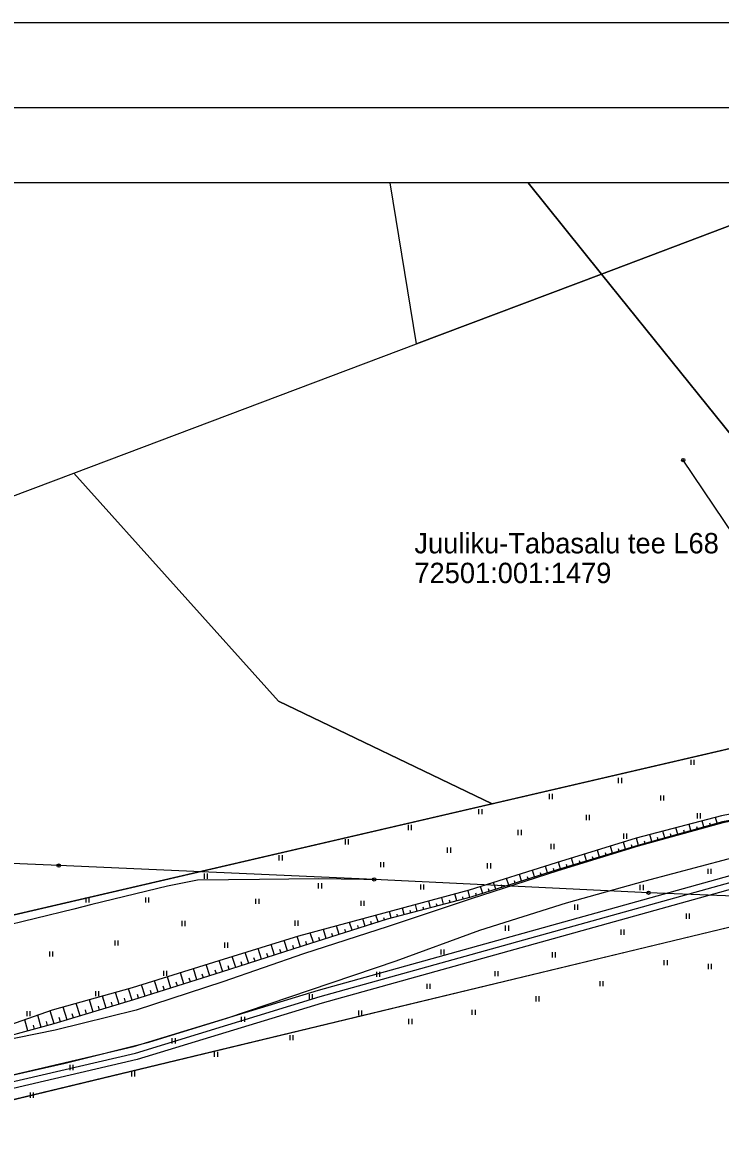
# Model space of a CAD drawing. Extents: x 532656 to 533339, y 6581345 to 6581629.
# Drawn here: x 533136.1 to 533238.9, y 6581463.1 to 6581629 of the extents above; entities that cross this region are included whole.
import ezdxf

# ---------------------------------------------------------------- set-up
doc = ezdxf.new("R2010")
doc.units = 0
for name, color, linetype in [('HALJASTUS', 7, 'Continuous'), ('KASUTUSALA', 7, 'Continuous'), ('KPOHULIIN', 7, 'Continuous'), ('MPKAABEL', 7, 'Continuous'), ('MPOHULIIN', 7, 'Continuous'), ('PIIR', 7, 'Continuous'), ('POST', 7, 'Continuous'), ('PR_SIDE', 7, 'Continuous'), ('RELJEEF', 7, 'Continuous'), ('TEE', 7, 'Continuous'), ('VORMISTUS', 7, 'Continuous')]:
    doc.layers.add(name, color=color, linetype=linetype)

msp = doc.modelspace()

# ---------------------------------------------------------------- linework, layer by layer
at = {"layer": 'HALJASTUS'}
for p, q in [((533234.5, 6581520.45), (533234.5, 6581519.69)), ((533234.96, 6581520.45), (533234.96, 6581519.69)), ((533223.82, 6581517.79), (533223.82, 6581517.03)), ((533224.28, 6581517.79), (533224.28, 6581517.03)), ((533213.65, 6581515.43), (533213.65, 6581514.67)), ((533214.11, 6581515.43), (533214.11, 6581514.67)), ((533230.03, 6581515.22), (533230.03, 6581514.46)), ((533230.48, 6581515.22), (533230.48, 6581514.46)), ((533203.27, 6581513.19), (533203.27, 6581512.43)), ((533203.73, 6581513.19), (533203.73, 6581512.43)), ((533219.1, 6581512.34), (533219.1, 6581511.57)), ((533219.55, 6581512.34), (533219.55, 6581511.57)), ((533235.43, 6581512.58), (533235.43, 6581511.82)), ((533235.88, 6581512.58), (533235.88, 6581511.82)), ((533192.89, 6581510.87), (533192.89, 6581510.11)), ((533193.35, 6581510.87), (533193.35, 6581510.11)), ((533183.61, 6581508.76), (533183.61, 6581508)), ((533184.06, 6581508.76), (533184.06, 6581508)), ((533209.05, 6581510.12), (533209.05, 6581509.36)), ((533209.51, 6581510.12), (533209.51, 6581509.36)), ((533224.58, 6581509.58), (533224.58, 6581508.82)), ((533225.04, 6581509.58), (533225.04, 6581508.82)), ((533198.64, 6581507.53), (533198.64, 6581506.77)), ((533199.1, 6581507.53), (533199.1, 6581506.77)), ((533213.91, 6581508.06), (533213.91, 6581507.3)), ((533214.36, 6581508.06), (533214.36, 6581507.3)), ((533173.86, 6581506.39), (533173.86, 6581505.63)), ((533174.32, 6581506.39), (533174.32, 6581505.63)), ((533188.82, 6581505.39), (533188.82, 6581504.63)), ((533189.28, 6581505.39), (533189.28, 6581504.63)), ((533162.85, 6581503.69), (533162.85, 6581502.93)), ((533163.3, 6581503.69), (533163.3, 6581502.93)), ((533204.54, 6581505.23), (533204.54, 6581504.47)), ((533204.99, 6581505.23), (533204.99, 6581504.47)), ((533237.02, 6581504.41), (533237.02, 6581503.65)), ((533237.48, 6581504.41), (533237.48, 6581503.65)), ((533179.66, 6581502.29), (533179.66, 6581501.52)), ((533180.12, 6581502.29), (533180.12, 6581501.52)), ((533194.71, 6581502.11), (533194.71, 6581501.34)), ((533195.16, 6581502.11), (533195.16, 6581501.34)), ((533227.02, 6581502.04), (533227.02, 6581501.28)), ((533227.48, 6581502.04), (533227.48, 6581501.28)), ((533145.42, 6581500.18), (533145.42, 6581499.42)), ((533145.87, 6581500.18), (533145.87, 6581499.42)), ((533154.2, 6581500.18), (533154.2, 6581499.42)), ((533154.65, 6581500.18), (533154.65, 6581499.42)), ((533170.43, 6581499.99), (533170.43, 6581499.23)), ((533170.89, 6581499.99), (533170.89, 6581499.23)), ((533185.93, 6581499.7), (533185.93, 6581498.94)), ((533186.38, 6581499.7), (533186.38, 6581498.94)), ((533217.36, 6581499.13), (533217.36, 6581498.37)), ((533217.81, 6581499.13), (533217.81, 6581498.37)), ((533233.82, 6581497.82), (533233.82, 6581497.06)), ((533234.27, 6581497.82), (533234.27, 6581497.06)), ((533159.58, 6581496.74), (533159.58, 6581495.98)), ((533160.03, 6581496.74), (533160.03, 6581495.98)), ((533176.18, 6581496.79), (533176.18, 6581496.02)), ((533176.64, 6581496.79), (533176.64, 6581496.02)), ((533207.19, 6581496.05), (533207.19, 6581495.28)), ((533207.64, 6581496.05), (533207.64, 6581495.28)), ((533224.19, 6581495.45), (533224.19, 6581494.69)), ((533224.65, 6581495.45), (533224.65, 6581494.69)), ((533149.68, 6581493.86), (533149.68, 6581493.1)), ((533150.13, 6581493.86), (533150.13, 6581493.1)), ((533140.08, 6581492.23), (533140.08, 6581491.47)), ((533140.53, 6581492.23), (533140.53, 6581491.47)), ((533165.84, 6581493.53), (533165.84, 6581492.77)), ((533166.3, 6581493.53), (533166.3, 6581492.77)), ((533197.69, 6581492.54), (533197.69, 6581491.78)), ((533198.15, 6581492.54), (533198.15, 6581491.78)), ((533214.07, 6581492.12), (533214.07, 6581491.36)), ((533214.52, 6581492.12), (533214.52, 6581491.36)), ((533230.56, 6581490.95), (533230.56, 6581490.19)), ((533231.01, 6581490.95), (533231.01, 6581490.19)), ((533237.06, 6581490.41), (533237.06, 6581489.64)), ((533237.51, 6581490.41), (533237.51, 6581489.64)), ((533156.85, 6581489.4), (533156.85, 6581488.63)), ((533157.31, 6581489.4), (533157.31, 6581488.63)), ((533188.24, 6581489.25), (533188.24, 6581488.49)), ((533188.69, 6581489.25), (533188.69, 6581488.49)), ((533205.63, 6581489.33), (533205.63, 6581488.57)), ((533206.08, 6581489.33), (533206.08, 6581488.57)), ((533195.62, 6581487.47), (533195.62, 6581486.71)), ((533196.08, 6581487.47), (533196.08, 6581486.71)), ((533221.1, 6581487.86), (533221.1, 6581487.1)), ((533221.56, 6581487.86), (533221.56, 6581487.1)), ((533146.85, 6581486.4), (533146.85, 6581485.64)), ((533147.31, 6581486.4), (533147.31, 6581485.64)), ((533178.32, 6581485.95), (533178.32, 6581485.19)), ((533178.78, 6581485.95), (533178.78, 6581485.19)), ((533211.69, 6581485.63), (533211.69, 6581484.87)), ((533212.15, 6581485.63), (533212.15, 6581484.87)), ((533136.72, 6581483.44), (533136.72, 6581482.68)), ((533137.18, 6581483.44), (533137.18, 6581482.68)), ((533168.32, 6581482.62), (533168.32, 6581481.86)), ((533168.78, 6581482.62), (533168.78, 6581481.86)), ((533185.58, 6581483.55), (533185.58, 6581482.79)), ((533186.04, 6581483.55), (533186.04, 6581482.79)), ((533192.96, 6581482.29), (533192.96, 6581481.53)), ((533193.41, 6581482.29), (533193.41, 6581481.53)), ((533202.28, 6581483.64), (533202.28, 6581482.88)), ((533202.74, 6581483.64), (533202.74, 6581482.88)), ((533158.11, 6581479.45), (533158.11, 6581478.69)), ((533158.56, 6581479.45), (533158.56, 6581478.69)), ((533175.45, 6581479.91), (533175.45, 6581479.15)), ((533175.91, 6581479.91), (533175.91, 6581479.15)), ((533164.35, 6581477.47), (533164.35, 6581476.7)), ((533164.81, 6581477.47), (533164.81, 6581476.7)), ((533143.09, 6581475.52), (533143.09, 6581474.76)), ((533143.54, 6581475.52), (533143.54, 6581474.76)), ((533152.16, 6581474.59), (533152.16, 6581473.83)), ((533152.61, 6581474.59), (533152.61, 6581473.83)), ((533137.22, 6581471.45), (533137.22, 6581470.68)), ((533137.67, 6581471.45), (533137.67, 6581470.68))]:
    msp.add_line(p, q, dxfattribs=at)
at = {"layer": 'KASUTUSALA'}
msp.add_lwpolyline([(533130.59, 6581473.14), (533152.46, 6581478.24), (533179.67, 6581486.55), (533283.32, 6581515.4), (533284.71, 6581513.71), (533180.23, 6581484.63), (533152.98, 6581476.31), (533130.88, 6581471.16)], dxfattribs=at)
at = {"layer": 'KPOHULIIN'}
msp.add_lwpolyline([(533284.7, 6581494.9), (533275.32, 6581502.37), (533233.4, 6581564.58)], dxfattribs=at)
at = {"layer": 'MPKAABEL'}
msp.add_lwpolyline([(533187.88, 6581502.84), (533186.34, 6581502.82), (533179.65, 6581502.93), (533170.99, 6581502.81), (533161.86, 6581502.74), (533157.45, 6581501.85), (533146.33, 6581499.15), (533143.65, 6581498.48), (533132.32, 6581495.71), (533125.95, 6581494.5), (533114.52, 6581495.45), (533102.79, 6581496.92), (533089.47, 6581498.82), (533077.24, 6581500), (533065.63, 6581501.23), (533053.69, 6581502.51), (533042.29, 6581503.73), (533032.02, 6581504.88), (533032.28, 6581506.42), (533031.89, 6581506.81)], dxfattribs=at)
msp.add_lwpolyline([(533187.88, 6581502.84), (533186.34, 6581502.82), (533179.65, 6581502.93), (533170.99, 6581502.81), (533161.86, 6581502.74), (533157.45, 6581501.85), (533146.33, 6581499.15), (533143.65, 6581498.48), (533132.32, 6581495.71), (533125.95, 6581494.5), (533114.52, 6581495.45), (533102.79, 6581496.92), (533089.47, 6581498.82), (533077.24, 6581500), (533065.63, 6581501.23), (533053.69, 6581502.51), (533042.29, 6581503.73), (533032.02, 6581504.88), (533032.28, 6581506.42), (533031.89, 6581506.81)], dxfattribs=at)
at = {"layer": 'MPOHULIIN'}
msp.add_lwpolyline([(533275.32, 6581502.37), (533268.53, 6581499.28), (533228.29, 6581500.87), (533187.88, 6581502.84), (533141.43, 6581504.88), (533095.45, 6581506.85), (533050.54, 6581508.81), (533010.87, 6581510.54), (532997.7, 6581528.31)], dxfattribs=at)
at = {"layer": 'PIIR'}
for points in [[(532997.7, 6581558.35), (533016.96, 6581555.16), (533066.33, 6581546.98), (533091.13, 6581542.87), (533143.65, 6581562.67), (533194.1, 6581581.68), (533190.24, 6581605.42)], [(533210.54, 6581605.42), (533221.38, 6581591.97), (533194.1, 6581581.68), (533190.24, 6581605.42)], [(533256.87, 6581605.42), (533221.38, 6581591.97), (533210.54, 6581605.42)], [(533261.48, 6581605.42), (533291.41, 6581534.01), (533271.76, 6581529.44), (533221.38, 6581591.97), (533256.87, 6581605.42)], [(532997.7, 6581558.35), (533016.96, 6581555.16), (533011.51, 6581513.79), (533060.19, 6581508.02), (533066.33, 6581546.98), (533091.13, 6581542.87), (533143.65, 6581562.67), (533173.8, 6581529.09), (533205.25, 6581513.98), (533125.12, 6581495.35), (532997.7, 6581510.35)], [(532997.7, 6581510.35), (533125.12, 6581495.35), (533271.76, 6581529.44), (533289.68, 6581507.68), (533127.07, 6581468.59), (533126.77, 6581469.47), (532997.7, 6581484.84)], [(533141.13, 6581421.68), (533127.07, 6581468.59), (533267.77, 6581502.5), (533292.38, 6581484.15), (533309.59, 6581464.94)]]:
    msp.add_lwpolyline(points, dxfattribs=at)
msp.add_lwpolyline([(533221.38, 6581591.97), (533271.76, 6581529.44), (533205.25, 6581513.98), (533173.8, 6581529.09), (533143.65, 6581562.67), (533194.1, 6581581.68)], close=True, dxfattribs=at)
at = {"layer": 'POST'}
for centre, radius in [((533233.4, 6581564.58), 0.25), ((533233.4, 6581564.58), 0.0234), ((533141.43, 6581504.88), 0.25), ((533141.43, 6581504.88), 0.0234), ((533187.88, 6581502.84), 0.25), ((533187.88, 6581502.84), 0.0234), ((533228.29, 6581500.87), 0.25)]:
    msp.add_circle(centre, radius, dxfattribs=at)
at = {"layer": 'PR_SIDE'}
msp.add_lwpolyline([(533009.76, 6581491.73), (533020.32, 6581490.23), (533026.33, 6581489.11), (533037.71, 6581487.73), (533062.59, 6581483.65), (533088.35, 6581480.21), (533108.95, 6581471.92), (533120.75, 6581471.5), (533130.73, 6581472.15), (533152.72, 6581477.27), (533179.95, 6581485.59), (533320.87, 6581524.82)], dxfattribs=at)
at = {"layer": 'RELJEEF'}
for p, q in [((533238.37, 6581511.11), (533238.13, 6581511.97)), ((533232.6, 6581509.48), (533232.32, 6581510.45)), ((533234.52, 6581510.02), (533234.26, 6581510.95)), ((533235.48, 6581510.3), (533235.4, 6581510.6)), ((533236.45, 6581510.57), (533236.19, 6581511.46)), ((533237.41, 6581510.84), (533237.33, 6581511.13)), ((533226.82, 6581507.85), (533226.52, 6581508.92)), ((533228.75, 6581508.4), (533228.46, 6581509.43)), ((533229.71, 6581508.67), (533229.61, 6581509.01)), ((533230.67, 6581508.94), (533230.39, 6581509.94)), ((533231.63, 6581509.21), (533231.54, 6581509.54)), ((533233.56, 6581509.75), (533233.47, 6581510.07)), ((533221.07, 6581506.14), (533220.77, 6581507.14)), ((533222.99, 6581506.71), (533222.68, 6581507.73)), ((533223.95, 6581506.99), (533223.84, 6581507.34)), ((533224.91, 6581507.28), (533224.59, 6581508.33)), ((533225.86, 6581507.57), (533225.76, 6581507.92)), ((533227.78, 6581508.12), (533227.69, 6581508.47)), ((533215.33, 6581504.42), (533215.04, 6581505.37)), ((533217.24, 6581504.99), (533216.95, 6581505.96)), ((533218.2, 6581505.28), (533218.1, 6581505.6)), ((533219.16, 6581505.56), (533218.86, 6581506.55)), ((533220.12, 6581505.85), (533220.02, 6581506.18)), ((533222.03, 6581506.42), (533221.93, 6581506.76)), ((533211.51, 6581503.21), (533211.2, 6581504.18)), ((533212.46, 6581503.52), (533212.36, 6581503.83)), ((533213.42, 6581503.82), (533213.11, 6581504.77)), ((533214.37, 6581504.12), (533214.27, 6581504.44)), ((533216.28, 6581504.7), (533216.19, 6581505.02)), ((533205.79, 6581501.39), (533205.47, 6581502.4)), ((533206.75, 6581501.7), (533206.64, 6581502.03)), ((533207.7, 6581502), (533207.38, 6581502.99)), ((533208.65, 6581502.3), (533208.55, 6581502.63)), ((533209.6, 6581502.61), (533209.29, 6581503.58)), ((533210.56, 6581502.91), (533210.45, 6581503.23)), ((533200.04, 6581499.69), (533199.78, 6581500.71)), ((533201.98, 6581500.19), (533201.71, 6581501.23)), ((533202.93, 6581500.49), (533202.83, 6581500.83)), ((533203.89, 6581500.79), (533203.56, 6581501.8)), ((533204.84, 6581501.09), (533204.73, 6581501.43)), ((533194.24, 6581498.17), (533193.98, 6581499.15)), ((533195.2, 6581498.42), (533195.12, 6581498.75)), ((533196.17, 6581498.68), (533195.91, 6581499.67)), ((533197.14, 6581498.93), (533197.05, 6581499.26)), ((533198.11, 6581499.18), (533197.84, 6581500.19)), ((533199.08, 6581499.43), (533198.99, 6581499.77)), ((533201.01, 6581499.94), (533200.92, 6581500.28)), ((533186.55, 6581495.97), (533186.21, 6581497.04)), ((533188.45, 6581496.58), (533188.14, 6581497.57)), ((533189.41, 6581496.89), (533189.3, 6581497.2)), ((533190.37, 6581497.16), (533190.12, 6581498.1)), ((533191.33, 6581497.41), (533191.25, 6581497.73)), ((533192.3, 6581497.67), (533192.05, 6581498.62)), ((533193.27, 6581497.92), (533193.19, 6581498.24)), ((533180.83, 6581494.14), (533180.41, 6581495.48)), ((533182.74, 6581494.75), (533182.34, 6581496)), ((533183.69, 6581495.06), (533183.56, 6581495.46)), ((533184.64, 6581495.36), (533184.27, 6581496.52)), ((533185.6, 6581495.67), (533185.48, 6581496.04)), ((533187.5, 6581496.28), (533187.39, 6581496.62)), ((533175.12, 6581492.31), (533174.63, 6581493.83)), ((533177.02, 6581492.93), (533176.54, 6581494.42)), ((533177.98, 6581493.23), (533177.82, 6581493.72)), ((533178.93, 6581493.54), (533178.47, 6581494.95)), ((533179.88, 6581493.84), (533179.73, 6581494.3)), ((533181.79, 6581494.45), (533181.65, 6581494.88)), ((533169.41, 6581490.47), (533168.89, 6581492.07)), ((533171.31, 6581491.09), (533170.81, 6581492.66)), ((533173.22, 6581491.7), (533172.72, 6581493.25)), ((533174.17, 6581492.01), (533174, 6581492.52)), ((533176.07, 6581492.62), (533175.91, 6581493.12)), ((533165.6, 6581489.25), (533165.07, 6581490.89)), ((533167.5, 6581489.86), (533166.98, 6581491.48)), ((533168.46, 6581490.17), (533168.28, 6581490.7)), ((533170.36, 6581490.78), (533170.19, 6581491.31)), ((533172.26, 6581491.39), (533172.1, 6581491.91)), ((533159.88, 6581487.45), (533159.36, 6581489.1)), ((533161.79, 6581488.05), (533161.26, 6581489.7)), ((533162.74, 6581488.35), (533162.57, 6581488.9)), ((533163.69, 6581488.65), (533163.17, 6581490.3)), ((533164.65, 6581488.95), (533164.47, 6581489.5)), ((533166.55, 6581489.56), (533166.38, 6581490.1)), ((533154.15, 6581485.65), (533153.63, 6581487.31)), ((533156.06, 6581486.25), (533155.54, 6581487.91)), ((533157.02, 6581486.55), (533156.84, 6581487.1)), ((533157.97, 6581486.85), (533157.45, 6581488.51)), ((533158.92, 6581487.15), (533158.75, 6581487.7)), ((533160.83, 6581487.75), (533160.66, 6581488.3)), ((533148.42, 6581483.89), (533147.88, 6581485.66)), ((533150.33, 6581484.47), (533149.81, 6581486.2)), ((533152.25, 6581485.05), (533151.73, 6581486.74)), ((533153.2, 6581485.35), (533153.03, 6581485.9)), ((533155.11, 6581485.95), (533154.93, 6581486.5)), ((533142.68, 6581482.15), (533142.1, 6581484.05)), ((533144.59, 6581482.73), (533144.03, 6581484.59)), ((533146.5, 6581483.31), (533145.95, 6581485.12)), ((533147.46, 6581483.6), (533147.28, 6581484.2)), ((533149.38, 6581484.18), (533149.2, 6581484.76)), ((533151.29, 6581484.76), (533151.12, 6581485.33)), ((533136.9, 6581480.52), (533136.45, 6581482.18)), ((533138.83, 6581481.05), (533138.34, 6581482.85)), ((533140.76, 6581481.57), (533140.18, 6581483.49)), ((533141.72, 6581481.86), (533141.52, 6581482.5)), ((533143.63, 6581482.44), (533143.44, 6581483.06)), ((533145.55, 6581483.02), (533145.36, 6581483.63)), ((533137.87, 6581480.78), (533137.71, 6581481.36)), ((533139.8, 6581481.31), (533139.63, 6581481.93))]:
    msp.add_line(p, q, dxfattribs=at)
for points in [[(533281.18, 6581520.42), (533276.05, 6581519.36), (533263.6, 6581516.53), (533251.65, 6581514.59), (533239.04, 6581512.21), (533226.47, 6581508.91), (533214.68, 6581505.26), (533201.89, 6581501.28), (533176.76, 6581494.49), (533164.99, 6581490.87), (533152.25, 6581486.88), (533140.46, 6581483.59), (533129.53, 6581479.74), (533118.62, 6581478.85), (533106.28, 6581479.43), (533097.7, 6581480.38), (533085.54, 6581482.56), (533072.44, 6581484.31), (533059.43, 6581486.03), (533046.01, 6581487.79), (533038.24, 6581488.57), (533036.77, 6581489.1), (533035.51, 6581491.06)], [(533281.56, 6581519.42), (533276.26, 6581518.13), (533263.82, 6581515.5), (533251.69, 6581513.67), (533239.15, 6581511.33), (533226.72, 6581507.82), (533214.83, 6581504.27), (533202.1, 6581500.22), (533189.78, 6581497.01), (533177.29, 6581493.01), (533165.35, 6581489.17), (533152.46, 6581485.11), (533140.73, 6581481.56), (533129.52, 6581478.53), (533118.47, 6581477.73), (533106, 6581477.89), (533097.29, 6581479.13), (533084.98, 6581481.19), (533071.98, 6581482.38), (533058.89, 6581484.14), (533045.84, 6581486.18), (533037.75, 6581487.16), (533036.17, 6581488.64), (533035.51, 6581491.06)]]:
    msp.add_lwpolyline(points, dxfattribs=at)
at = {"layer": 'TEE'}
for points in [[(533282.01, 6581518.32), (533276.57, 6581517.43), (533263.84, 6581515.34), (533251.71, 6581513.56), (533239.21, 6581511.18), (533226.77, 6581507.72), (533214.91, 6581504.11), (533202.18, 6581499.97), (533189.93, 6581495.93), (533177.46, 6581491.89), (533165.59, 6581487.75), (533152.84, 6581483.6), (533140.89, 6581480.63), (533129.55, 6581478.32)], [(533130.59, 6581473.14), (533142.41, 6581475.8), (533154.7, 6581478.86), (533166.17, 6581482.42), (533178.5, 6581486.6), (533191.1, 6581490.85), (533203.46, 6581495.37), (533216.21, 6581499.38), (533227.79, 6581502.65), (533240.03, 6581505.88), (533252.31, 6581508.35), (533264.03, 6581510.19), (533276.86, 6581512.43), (533282.67, 6581513.71)]]:
    msp.add_lwpolyline(points, dxfattribs=at)
at = {"layer": 'VORMISTUS'}
for points in [[(532967.7, 6581629.01), (533338.95, 6581629.01), (533338.95, 6581366.51), (532967.7, 6581366.51)], [(532981.45, 6581379.01), (532981.45, 6581616.51), (533325.2, 6581616.51), (533325.2, 6581379.01)], [(532981.45, 6581616.51), (533325.2, 6581616.51), (533325.2, 6581379.01), (532981.45, 6581379.01)], [(533309.59, 6581421.68), (533309.59, 6581605.42), (532997.7, 6581605.42), (532997.7, 6581421.68)]]:
    msp.add_lwpolyline(points, close=True, dxfattribs=at)
msp.add_lwpolyline([(533309.59, 6581605.42), (532997.7, 6581605.42)], dxfattribs=at)

# ---------------------------------------------------------------- texts
at = {"layer": 'PIIR'}
for s, p in [('Juuliku-Tabasalu tee L68', (533193.81, 6581550.85)), ('72501:001:1479', (533193.81, 6581546.47))]:
    msp.add_text(s, height=3, dxfattribs=at).set_placement(p)

doc.saveas('drawing.dxf')
